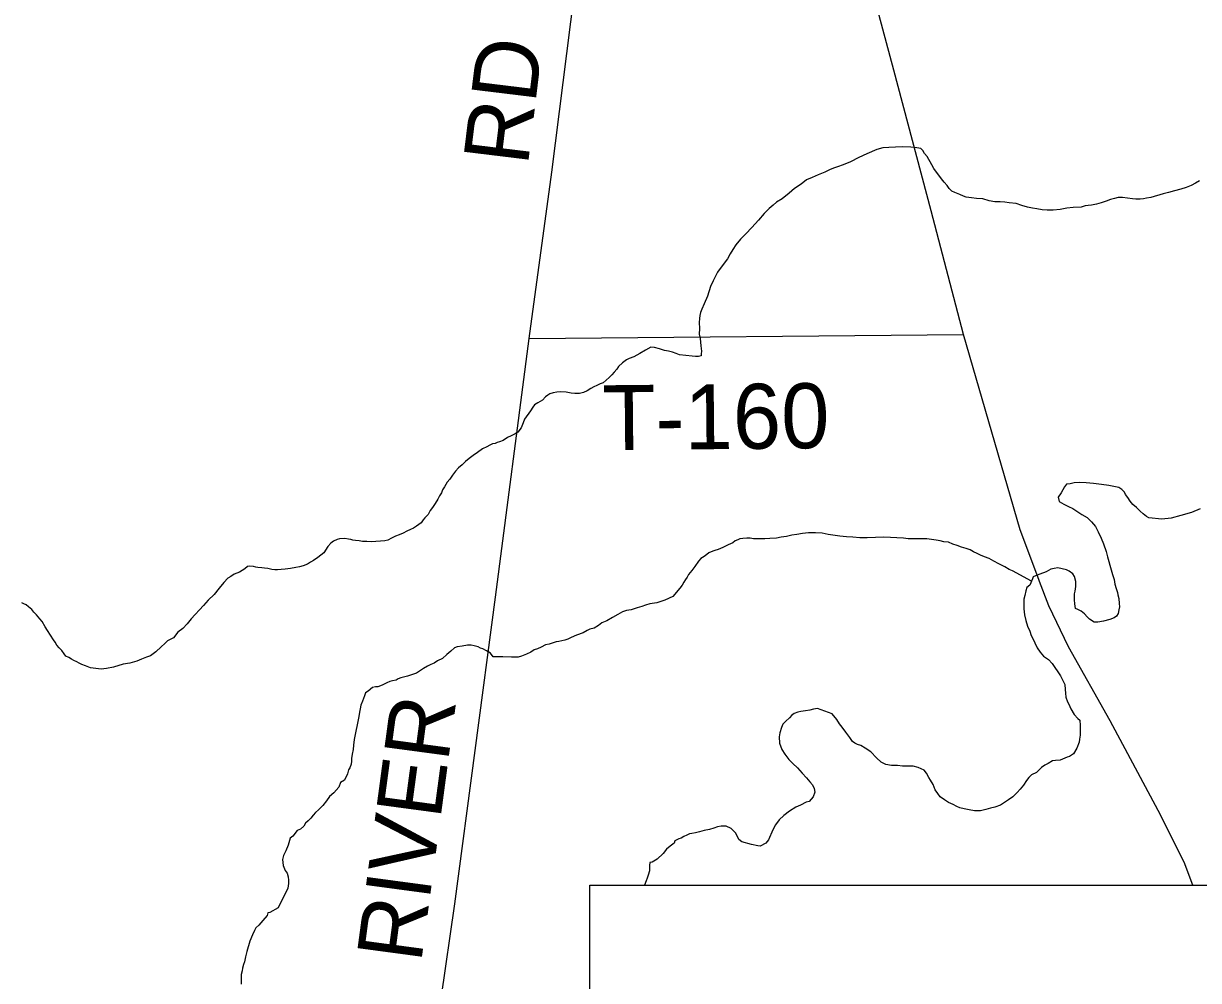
# Model space of a CAD drawing. Extents: x 0 to 34, y 0 to 22.
# Drawn here: x 3.195 to 4.222, y 15.642 to 16.479 of the extents above; entities that cross this region are included whole.
import ezdxf

# ---------------------------------------------------------------- set-up
doc = ezdxf.new("R2010")
doc.units = 0
for name, color, linetype in [('GM_X_Corporation', 7, 'Continuous'), ('GM_X_County_Road', 7, 'Continuous'), ('GM_X_County_Road_Text', 7, 'Continuous'), ('GM_X_Minor_River', 7, 'Continuous'), ('GM_X_Township_Road', 7, 'Continuous'), ('GM_X_Township_Road_Text', 7, 'Continuous'), ('SH_Text', 7, 'Continuous')]:
    doc.layers.add(name, color=color, linetype=linetype)

msp = doc.modelspace()

# ---------------------------------------------------------------- linework, layer by layer
at = {"layer": 'GM_X_Corporation'}
msp.add_lwpolyline([(3.6901, 15.2048), (3.6901, 15.7256), (5.9099, 15.7256), (5.9099, 15.2138)], dxfattribs=at)
at = {"layer": 'GM_X_County_Road'}
msp.add_lwpolyline([(3.5195, 15.1803), (3.5207, 15.2006), (3.5211, 15.2036), (3.5293, 15.2558), (3.5414, 15.3335), (3.5433, 15.3555), (3.5444, 15.384), (3.544, 15.4372), (3.5428, 15.4611), (3.5426, 15.4998), (3.5435, 15.5143), (3.548, 15.5436), (3.572, 15.7092), (3.6074, 15.9775), (3.6369, 16.2036), (3.6567, 16.349), (3.7031, 16.7163), (3.7483, 17.0786), (3.7604, 17.1798), (3.7595, 17.1946), (3.7574, 17.3264), (3.7557, 17.5159), (3.7523, 17.7146)], dxfattribs=at)
at = {"layer": 'GM_X_Minor_River'}
for points in [[(3.9826, 16.3655), (3.9812, 16.3681), (3.9793, 16.3697), (3.9759, 16.3705), (3.9706, 16.3709), (3.9637, 16.3714), (3.9572, 16.3711), (3.9515, 16.3708), (3.9462, 16.3705), (3.9409, 16.369), (3.9321, 16.3653), (3.9252, 16.362), (3.9179, 16.3582), (3.9114, 16.3557), (3.9065, 16.3538), (3.903, 16.3527), (3.8996, 16.3512), (3.8954, 16.349), (3.8897, 16.3468), (3.8843, 16.3446), (3.8794, 16.3424), (3.8747, 16.3386), (3.869, 16.3349), (3.8644, 16.3308), (3.8582, 16.3259), (3.8533, 16.3229), (3.8502, 16.3203), (3.8467, 16.3173), (3.8425, 16.3131), (3.8375, 16.3071), (3.8317, 16.3007), (3.8263, 16.2951), (3.8217, 16.2906), (3.8178, 16.2857), (3.8151, 16.2815), (3.8128, 16.2778), (3.8105, 16.2732), (3.8031, 16.2638), (3.8016, 16.2616), (3.8, 16.2581), (3.7977, 16.254), (3.7954, 16.2491), (3.793, 16.2407), (3.7899, 16.2339), (3.7879, 16.2294), (3.7867, 16.2264), (3.7863, 16.2237), (3.7859, 16.2211), (3.7855, 16.2177), (3.7858, 16.2123), (3.7857, 16.2074), (3.7865, 16.2036), (3.7868, 16.2005), (3.7871, 16.1971), (3.7875, 16.1925), (3.7874, 16.1903), (3.7874, 16.1884), (3.7851, 16.188), (3.7825, 16.188), (3.7794, 16.1881), (3.7684, 16.1893), (3.7654, 16.1905), (3.7624, 16.1917), (3.7589, 16.1925), (3.7552, 16.1933), (3.751, 16.1945), (3.7464, 16.1957), (3.7434, 16.1961), (3.7388, 16.1935), (3.7338, 16.1905), (3.7285, 16.1875), (3.7243, 16.1861), (3.722, 16.185), (3.7185, 16.1823), (3.7151, 16.1793), (3.7135, 16.1767), (3.7112, 16.1741), (3.7093, 16.1718), (3.707, 16.1695), (3.7043, 16.1673), (3.7016, 16.165), (3.6989, 16.1639), (3.6962, 16.1625), (3.6936, 16.1613), (3.6909, 16.1599), (3.6878, 16.158), (3.6844, 16.1565), (3.681, 16.1554), (3.6768, 16.1555), (3.6737, 16.1559), (3.6692, 16.1567), (3.6646, 16.1571), (3.6612, 16.1568), (3.6578, 16.1561), (3.6551, 16.1553), (3.6532, 16.1542), (3.6513, 16.1527), (3.6486, 16.1497), (3.6444, 16.1475), (3.6417, 16.1456), (3.6401, 16.1437)], [(4.223, 16.3417), (4.2195, 16.3395), (4.2157, 16.3376), (4.2115, 16.3358), (4.2069, 16.3343), (4.2012, 16.3328), (4.1959, 16.3314), (4.1913, 16.3303), (4.1806, 16.327), (4.1768, 16.3263), (4.1741, 16.3259), (4.1711, 16.3256), (4.1673, 16.3256), (4.1646, 16.3257), (4.1601, 16.3265), (4.1559, 16.3269), (4.1521, 16.327), (4.1487, 16.3262), (4.1452, 16.3251), (4.1414, 16.3237), (4.1372, 16.3222), (4.133, 16.3211), (4.1288, 16.3204), (4.1258, 16.32), (4.1231, 16.3197), (4.1197, 16.3186), (4.1125, 16.3183), (4.1071, 16.3176), (4.1014, 16.3165), (4.095, 16.3159), (4.09, 16.3159), (4.0855, 16.3163), (4.0809, 16.3172), (4.0771, 16.3176), (4.0726, 16.3184), (4.0676, 16.32), (4.0627, 16.3216), (4.0566, 16.3224), (4.0528, 16.3228), (4.0487, 16.3232), (4.0441, 16.3233), (4.0392, 16.3241), (4.0335, 16.3257), (4.0282, 16.3261), (4.0236, 16.3266), (4.0213, 16.327), (4.0191, 16.3274), (4.0168, 16.3282), (4.0134, 16.3297), (4.0092, 16.3313), (4.0066, 16.3325), (4.0043, 16.3348), (4.0025, 16.3375), (3.9998, 16.3405), (3.9976, 16.3432), (3.9909, 16.3524), (3.989, 16.3555), (3.9875, 16.3582), (3.9864, 16.3601), (3.9849, 16.3628), (3.9826, 16.3655)], [(3.6401, 16.1437), (3.6382, 16.1403), (3.6328, 16.1332), (3.6316, 16.1298), (3.63, 16.1256), (3.6269, 16.1218), (3.6247, 16.1203), (3.6212, 16.1185), (3.6181, 16.117), (3.6143, 16.1144), (3.6109, 16.1133), (3.609, 16.1126), (3.6071, 16.1118), (3.6048, 16.1115), (3.6025, 16.1103), (3.5998, 16.1089), (3.596, 16.107), (3.5918, 16.104), (3.5879, 16.1014), (3.5845, 16.0988), (3.5814, 16.0962), (3.5783, 16.0931), (3.5753, 16.0905), (3.5726, 16.0875), (3.5699, 16.0841), (3.5675, 16.0807), (3.5652, 16.0781), (3.5629, 16.0739), (3.5613, 16.0713), (3.5602, 16.0687), (3.5586, 16.066), (3.5571, 16.063), (3.5547, 16.0592), (3.5524, 16.0558), (3.5505, 16.0532), (3.5485, 16.0498), (3.5458, 16.0468), (3.5443, 16.0449), (3.5424, 16.0423), (3.5385, 16.0396), (3.5358, 16.0378), (3.5332, 16.0367), (3.5301, 16.0352), (3.5267, 16.0333), (3.5232, 16.0318), (3.5202, 16.0307), (3.5167, 16.0289), (3.5133, 16.0274), (3.5106, 16.0267), (3.4992, 16.0257), (3.495, 16.0261), (3.4912, 16.0261), (3.4882, 16.0266), (3.4852, 16.027), (3.4829, 16.0274), (3.481, 16.0278), (3.4791, 16.0282), (3.4757, 16.0286), (3.4711, 16.0283), (3.4692, 16.0279), (3.4658, 16.0264), (3.4635, 16.0246), (3.4608, 16.0216), (3.4573, 16.0163), (3.4523, 16.0122), (3.4484, 16.0095), (3.4458, 16.0081), (3.4431, 16.0062), (3.4393, 16.0047), (3.4362, 16.004), (3.4328, 16.0033), (3.4282, 16.0026), (3.4236, 16.0019), (3.4202, 16.0015), (3.4168, 16.0012), (3.4145, 16.0012), (3.4119, 16.0016), (3.4084, 16.0024), (3.4054, 16.0028), (3.4031, 16.0032), (3.3997, 16.0033), (3.3978, 16.0037), (3.3959, 16.0041), (3.3925, 16.0045), (3.3906, 16.0041), (3.3883, 16.0023), (3.3837, 15.9993), (3.3791, 15.9974), (3.3761, 15.9956), (3.3734, 15.9941), (3.3699, 15.9903), (3.366, 15.9854), (3.3614, 15.9798), (3.3564, 15.9749), (3.3522, 15.97), (3.3414, 15.9584), (3.3379, 15.9542), (3.3341, 15.9501), (3.3298, 15.9467), (3.326, 15.9418), (3.3206, 15.9392)], [(4.2237, 16.0547), (4.2161, 16.0514), (4.2069, 16.0488), (4.1982, 16.0466), (4.1902, 16.0456), (4.1788, 16.0469), (4.1769, 16.048), (4.1739, 16.0503), (4.1712, 16.0527), (4.1679, 16.0557), (4.1648, 16.0584), (4.1626, 16.0615), (4.1604, 16.0646), (4.1585, 16.0673), (4.1574, 16.0692), (4.1551, 16.0715), (4.1525, 16.0734), (4.1483, 16.0742), (4.1438, 16.075), (4.1373, 16.0759), (4.1305, 16.0767), (4.124, 16.0775), (4.1179, 16.0776), (4.1134, 16.0773), (4.1099, 16.0766), (4.1069, 16.0762), (4.105, 16.074), (4.1022, 16.0687), (4.0995, 16.0649), (4.1003, 16.0611), (4.1044, 16.0588), (4.1086, 16.0568), (4.1123, 16.0549), (4.1157, 16.0526), (4.1203, 16.0498), (4.1248, 16.0471), (4.1286, 16.0433), (4.1323, 16.0391), (4.1345, 16.0345), (4.1371, 16.0291), (4.1393, 16.0241), (4.1415, 16.0173), (4.1426, 16.0127), (4.1459, 16.0013), (4.147, 15.9971), (4.1485, 15.9929), (4.1492, 15.9887), (4.1503, 15.9849), (4.1514, 15.9814), (4.1517, 15.9795), (4.1525, 15.9761), (4.1528, 15.9719), (4.1531, 15.9689), (4.1527, 15.9662), (4.1519, 15.9632), (4.1504, 15.9609), (4.1484, 15.9594), (4.1446, 15.9579), (4.1393, 15.9565), (4.1343, 15.9554), (4.1309, 15.9554), (4.1268, 15.9582), (4.1249, 15.9601), (4.1226, 15.9628), (4.1196, 15.9651), (4.1166, 15.9666), (4.1147, 15.9674), (4.114, 15.9716), (4.1137, 15.975), (4.1137, 15.9777), (4.1137, 15.9804), (4.1145, 15.9826), (4.1149, 15.9868), (4.115, 15.991), (4.1139, 15.9956), (4.1124, 15.9979), (4.109, 16.0002), (4.1068, 16.0013), (4.0992, 16.003), (4.0961, 16.0026), (4.0931, 16.0019), (4.0889, 15.9997), (4.0835, 15.9974), (4.0797, 15.996), (4.0778, 15.9952), (4.077, 15.9933), (4.0747, 15.988), (4.072, 15.9858)], [(4.0761, 15.9913), (4.0596, 16.0004), (4.0566, 16.0016), (4.0528, 16.0039), (4.0505, 16.0051), (4.0475, 16.0066), (4.0434, 16.0089), (4.0392, 16.0113), (4.0351, 16.0128), (4.0316, 16.014), (4.0286, 16.0156), (4.0256, 16.0171), (4.0226, 16.0187), (4.0192, 16.0199), (4.015, 16.0211), (4.0112, 16.0226), (4.0074, 16.0238), (4.0037, 16.0254), (3.9995, 16.0258), (3.9964, 16.0266), (3.9927, 16.0274), (3.9889, 16.0278), (3.9847, 16.0283), (3.9809, 16.0283), (3.9771, 16.0284), (3.9721, 16.0284), (3.9683, 16.0285), (3.9642, 16.0289), (3.9471, 16.0299), (3.9398, 16.0296), (3.9326, 16.0293), (3.9262, 16.0293), (3.9201, 16.0298), (3.9144, 16.0302), (3.9087, 16.0307), (3.9026, 16.0315), (3.8984, 16.0323), (3.8931, 16.0335), (3.8874, 16.0336), (3.8813, 16.0337), (3.876, 16.033), (3.8711, 16.0323), (3.8665, 16.0316), (3.8619, 16.0305), (3.8573, 16.0298), (3.8532, 16.0291), (3.8475, 16.0288), (3.8429, 16.0284), (3.8391, 16.0285), (3.8357, 16.0285), (3.833, 16.0285), (3.8303, 16.029), (3.8273, 16.029), (3.8239, 16.0287), (3.8212, 16.0283), (3.8193, 16.0276), (3.817, 16.0268), (3.8151, 16.025), (3.8109, 16.0231), (3.8063, 16.0209), (3.8021, 16.019), (3.7994, 16.0183), (3.7975, 16.0176), (3.7941, 16.0161), (3.7922, 16.0146), (3.7899, 16.0131), (3.7872, 16.0112), (3.7849, 16.009), (3.7818, 16.0041), (3.7791, 16.0007), (3.7764, 15.9973), (3.7752, 15.995), (3.7737, 15.9928), (3.7721, 15.9905), (3.7706, 15.9879), (3.7686, 15.9852), (3.7625, 15.9781), (3.7556, 15.9747), (3.7487, 15.9725), (3.7426, 15.9715), (3.7388, 15.9704), (3.7354, 15.9693), (3.7315, 15.9682), (3.7262, 15.9663), (3.722, 15.9656), (3.7186, 15.9645), (3.7144, 15.9623), (3.7098, 15.9597), (3.7048, 15.9567), (3.7006, 15.9549), (3.6975, 15.9526), (3.6937, 15.9504), (3.6899, 15.9493), (3.6876, 15.9482), (3.6841, 15.9463), (3.6784, 15.9441), (3.6738, 15.9422), (3.6708, 15.9408)], [(4.072, 15.9858), (4.0712, 15.9828), (4.0704, 15.979), (4.0696, 15.9756), (4.0695, 15.9718), (4.0695, 15.9672), (4.0702, 15.9619), (4.0713, 15.9569), (4.0727, 15.952), (4.0746, 15.9478), (4.076, 15.9439), (4.0775, 15.9413), (4.079, 15.9374), (4.0812, 15.9332), (4.0838, 15.9294), (4.0868, 15.9259), (4.091, 15.9229), (4.0944, 15.9194), (4.1015, 15.9087), (4.1037, 15.9045), (4.1052, 15.901), (4.1055, 15.8965), (4.1058, 15.8934), (4.1062, 15.89), (4.1077, 15.8858), (4.1088, 15.8839), (4.1106, 15.8797), (4.1136, 15.8747), (4.1166, 15.8712), (4.1185, 15.8697), (4.1188, 15.8651), (4.1188, 15.8606), (4.1187, 15.8568), (4.1183, 15.8533), (4.1179, 15.8507), (4.1159, 15.8454), (4.1128, 15.8405), (4.1094, 15.8379), (4.1075, 15.8375), (4.1013, 15.8349), (4.0972, 15.8346), (4.0945, 15.8342), (4.0907, 15.832), (4.088, 15.8305), (4.0849, 15.8283), (4.0807, 15.8241), (4.0761, 15.8219), (4.0738, 15.8197), (4.0719, 15.817), (4.0691, 15.8129), (4.0664, 15.8095), (4.0637, 15.8065), (4.0599, 15.8027), (4.0561, 15.8001), (4.0492, 15.7956), (4.0442, 15.7938), (4.0404, 15.7927), (4.0362, 15.7916), (4.0316, 15.7905), (4.0263, 15.7906), (4.0217, 15.7914), (4.0172, 15.7922), (4.0134, 15.793), (4.0108, 15.7942), (4.0077, 15.7961), (4.0036, 15.7977), (4.0002, 15.8), (3.9964, 15.8027), (3.9942, 15.8058), (3.9919, 15.8089), (3.9901, 15.8134), (3.9878, 15.8173), (3.9863, 15.8196), (3.9845, 15.8234), (3.9822, 15.8261), (3.977, 15.8284), (3.9728, 15.8296), (3.9678, 15.8297), (3.9633, 15.8297), (3.9591, 15.8301), (3.9538, 15.8302), (3.9489, 15.831), (3.9447, 15.833), (3.9406, 15.8368), (3.9357, 15.8422), (3.9308, 15.8453), (3.927, 15.8476), (3.924, 15.8484), (3.9217, 15.8496), (3.9198, 15.8511), (3.9172, 15.8546), (3.9138, 15.8592), (3.9105, 15.8638), (3.9082, 15.8665), (3.906, 15.8703), (3.9019, 15.8753), (3.889, 15.88), (3.8856, 15.8793), (3.8825, 15.8786), (3.8787, 15.8779), (3.8745, 15.8775)], [(3.3206, 15.9392), (3.3183, 15.937), (3.3153, 15.934), (3.3106, 15.9295), (3.3057, 15.9261), (3.3022, 15.925), (3.298, 15.9231), (3.2938, 15.9213), (3.2877, 15.9198), (3.282, 15.9188), (3.2736, 15.9162), (3.2675, 15.9151), (3.2626, 15.9144), (3.258, 15.9149), (3.2534, 15.9157), (3.2489, 15.9173), (3.2459, 15.9184), (3.2436, 15.9196), (3.2413, 15.9208), (3.2387, 15.9219), (3.2368, 15.9231), (3.2345, 15.9247), (3.2319, 15.9258), (3.2304, 15.9277), (3.2282, 15.9308), (3.2259, 15.9331), (3.224, 15.9354), (3.2225, 15.9381), (3.221, 15.94), (3.2184, 15.9442), (3.2158, 15.9481), (3.2136, 15.9515), (3.211, 15.9561), (3.2091, 15.9584), (3.2061, 15.9619), (3.2038, 15.9642), (3.202, 15.9665), (3.1993, 15.9688), (3.1971, 15.9707), (3.1952, 15.9715), (3.1933, 15.9723)], [(3.6708, 15.9408), (3.6681, 15.9397), (3.6654, 15.9393), (3.6628, 15.9386), (3.6605, 15.9382), (3.6578, 15.9375), (3.6544, 15.9364), (3.6513, 15.9357), (3.6475, 15.9338), (3.6441, 15.9323), (3.6414, 15.9312), (3.6383, 15.9294), (3.6345, 15.9275), (3.6303, 15.9257), (3.6272, 15.9249), (3.6215, 15.925), (3.6139, 15.9251), (3.6086, 15.9252), (3.6056, 15.9252), (3.603, 15.9283), (3.5996, 15.9306), (3.5965, 15.9321), (3.5943, 15.9329), (3.5924, 15.9341), (3.589, 15.9349), (3.5863, 15.9353), (3.5829, 15.9353), (3.5783, 15.9346), (3.5741, 15.9339), (3.5718, 15.9332), (3.5684, 15.9302), (3.5649, 15.9272), (3.5611, 15.9238), (3.5569, 15.9216), (3.5538, 15.9197), (3.5511, 15.9186), (3.5481, 15.9171), (3.5446, 15.9149), (3.5385, 15.9108), (3.5305, 15.9082), (3.5248, 15.9068), (3.5225, 15.906), (3.5206, 15.9049), (3.5175, 15.9042), (3.5152, 15.9035), (3.5125, 15.9024), (3.5083, 15.9005), (3.5045, 15.899), (3.5026, 15.899), (3.5, 15.8983), (3.4961, 15.8953), (3.4938, 15.8938), (3.493, 15.8912), (3.4911, 15.8863), (3.4899, 15.8829), (3.4891, 15.8798), (3.4887, 15.8768), (3.4879, 15.873), (3.4838, 15.8529), (3.4834, 15.848), (3.483, 15.8442), (3.4821, 15.84), (3.4817, 15.8362), (3.4817, 15.8339), (3.4813, 15.8313), (3.4801, 15.8282), (3.4789, 15.8263), (3.4781, 15.8229), (3.4754, 15.8173), (3.472, 15.8154), (3.4704, 15.8112), (3.4662, 15.8064), (3.4623, 15.803), (3.4596, 15.7992), (3.4565, 15.7951), (3.4527, 15.7913), (3.45, 15.7891), (3.4481, 15.7868), (3.4461, 15.7842), (3.4438, 15.7819), (3.4415, 15.7797), (3.44, 15.777), (3.4369, 15.7744), (3.4342, 15.7733), (3.4303, 15.7684), (3.428, 15.7665), (3.4261, 15.7605), (3.4241, 15.7555), (3.4222, 15.7514), (3.4214, 15.748), (3.4217, 15.7426), (3.4235, 15.7384), (3.4254, 15.7361), (3.4261, 15.7327), (3.4265, 15.73), (3.4264, 15.727), (3.426, 15.7228), (3.4174, 15.7058), (3.4102, 15.7017), (3.4083, 15.7014), (3.4078, 15.6991)], [(3.8745, 15.8775), (3.8719, 15.8768), (3.8688, 15.8757), (3.8665, 15.8742), (3.8646, 15.8719), (3.8615, 15.8689), (3.8588, 15.8663), (3.8576, 15.8633), (3.8561, 15.8587), (3.8556, 15.8553), (3.8559, 15.8496), (3.8578, 15.8443), (3.8604, 15.8401), (3.8641, 15.8355), (3.8675, 15.832), (3.8717, 15.8281), (3.8758, 15.8235), (3.8795, 15.8193), (3.8825, 15.8159), (3.8848, 15.8132), (3.8863, 15.8101), (3.8866, 15.8067), (3.8854, 15.8029), (3.8819, 15.7988), (3.8793, 15.798), (3.8743, 15.7954), (3.8701, 15.7936), (3.8647, 15.7902), (3.8597, 15.7865), (3.8555, 15.7827), (3.8524, 15.7782), (3.8501, 15.774), (3.8462, 15.765), (3.8439, 15.7623), (3.8389, 15.7597), (3.837, 15.7598), (3.8313, 15.761), (3.823, 15.7633), (3.8203, 15.7653), (3.8189, 15.7687), (3.8174, 15.7714), (3.8136, 15.7752), (3.8091, 15.7772), (3.8049, 15.7772), (3.8015, 15.7765), (3.7984, 15.7754), (3.7946, 15.7743), (3.79, 15.7732), (3.7858, 15.7721), (3.7824, 15.7714), (3.7793, 15.7707), (3.7771, 15.7703), (3.7748, 15.7692), (3.7721, 15.7681), (3.7698, 15.7666), (3.7679, 15.7659), (3.7644, 15.7644), (3.7637, 15.7621), (3.7602, 15.7595), (3.7571, 15.7569), (3.754, 15.7531), (3.749, 15.7483), (3.7445, 15.7456), (3.7425, 15.7453), (3.7421, 15.7426), (3.7421, 15.7381), (3.7409, 15.7343), (3.7401, 15.7316), (3.7393, 15.7294), (3.7378, 15.7256)], [(3.4078, 15.6991), (3.404, 15.6946), (3.4005, 15.6904), (3.3978, 15.6882), (3.3967, 15.6859), (3.3951, 15.6821), (3.3927, 15.6765), (3.39, 15.6674), (3.3888, 15.6628), (3.388, 15.6583), (3.3872, 15.656), (3.3864, 15.653), (3.386, 15.6507), (3.3852, 15.6473), (3.3851, 15.6389)]]:
    msp.add_lwpolyline(points, dxfattribs=at)
at = {"layer": 'GM_X_Township_Road'}
msp.add_line((3.6369, 16.2036), (4.0166, 16.2071), dxfattribs=at)
for points in [[(4.0826, 15.9928), (4.0662, 16.0363), (4.0166, 16.2071), (3.9886, 16.3154), (3.9558, 16.4385), (3.9249, 16.5538), (3.8676, 16.7702), (3.802, 17.0136), (3.7651, 17.1512), (3.7604, 17.1798)], [(4.2174, 15.7256), (4.2096, 15.7455), (4.1871, 15.7908), (4.145, 15.8692), (4.1085, 15.934), (4.0913, 15.9697), (4.0832, 15.991), (4.0826, 15.9928)]]:
    msp.add_lwpolyline(points, dxfattribs=at)
at = {"layer": 'SH_Text'}
msp.add_lwpolyline([(3.6901, 15.7256), (5.9099, 15.7256), (5.9099, 15.0085), (3.6901, 15.0085)], close=True, dxfattribs=at)

# ---------------------------------------------------------------- texts
at = {"layer": 'GM_X_County_Road_Text'}
for s, rotation, p in [('RD', 83.0591, (3.6357, 16.3539)), ('RIVER', 82.3617, (3.5424, 15.6567))]:
    msp.add_text(s, height=0.05682, rotation=rotation, dxfattribs=at).set_placement(p)
at = {"layer": 'GM_X_Township_Road_Text'}
msp.add_text('T-160', height=0.05682, rotation=0.5614, dxfattribs=at).set_placement((3.7013, 16.1059))

doc.saveas('drawing.dxf')
